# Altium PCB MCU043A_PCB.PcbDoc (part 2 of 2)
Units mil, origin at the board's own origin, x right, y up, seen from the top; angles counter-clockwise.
Board outline 3935 x 1020 mil, 2 copper layers (Top Layer, Bottom Layer), stack 62 mil thick; 69 components, 49 nets, 220 pads, 91 vias.
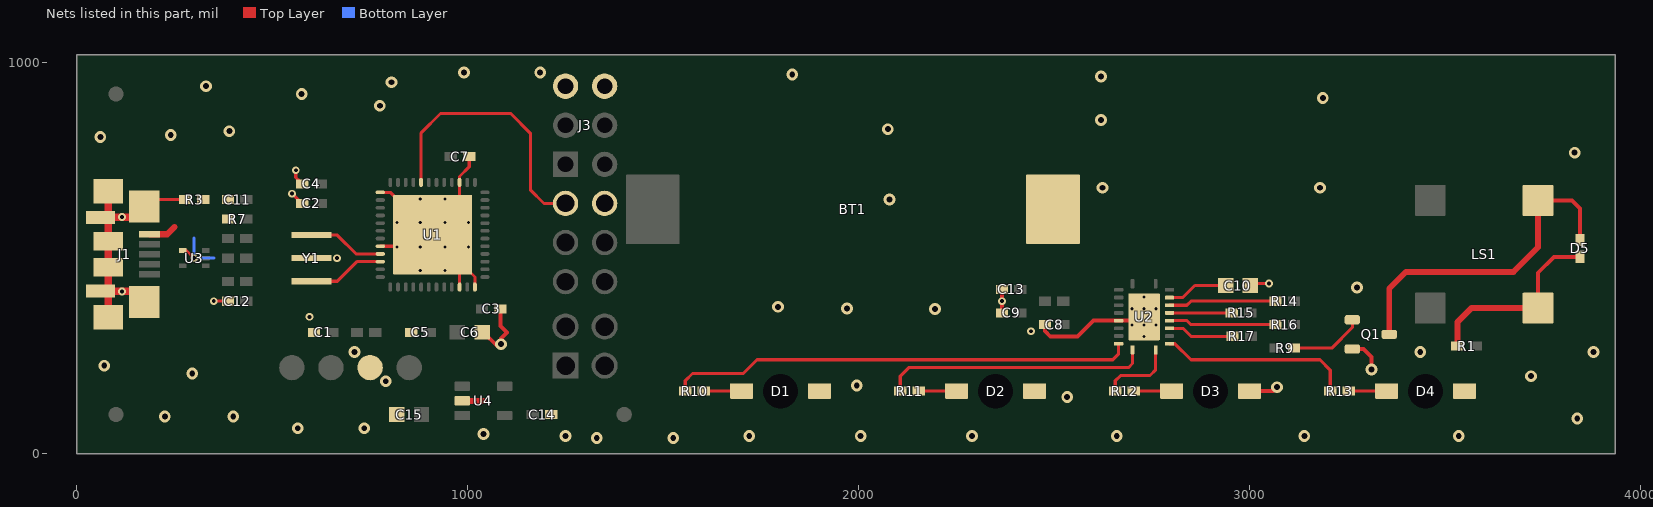
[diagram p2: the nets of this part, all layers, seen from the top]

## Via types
v1: diameter 30, hole 15, Top Layer to Bottom Layer, tented both sides, 51 vias
v2: diameter 19.68, hole 7.87, Top Layer to Bottom Layer, 20 vias
v3: diameter 20, hole 10, Top Layer to Bottom Layer, tented both sides, 20 vias

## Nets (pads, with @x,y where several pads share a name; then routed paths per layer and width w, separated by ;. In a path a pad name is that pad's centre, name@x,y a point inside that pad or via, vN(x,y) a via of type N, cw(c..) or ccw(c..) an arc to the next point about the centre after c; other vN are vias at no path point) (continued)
GND: C1.2 C2.2 C3.2 C4.2 C5.2 C6.2 C7.2 C11.2 C12.2 C14.2 C15.2 J1.5 J3.5 pad.1@750,220 R3.2 R7.1 U1.10 U1.12 U1.27 U1.37 U1.44 U1.49 U3.4 U4.2 Y1.2 | length 1260.8
  Top Layer w8: U3.4@270.47,519.68 280.32,519.68 v3(300,500) ; v3(350,390) C12.2@386.38,390 ; v3(550,665) 551.38,665 C2.2@576.38,640 ; v3(560,725) 560,706.38 570,696.38 C4.2@576.38,690 ; U1.44@776.14,530.47 880.47,530.47 U1.49@910,560 ; U1.37@776.14,668.27 801.73,668.27 v2(878.37,591.63) U1.49@910,560 ; U1.10@978.9,426.14 U1.49@978.9,489 ; U1.49@978.9,628.9 U1.27@978.9,693.86 978.9,708.9 1003.62,733.62 C7.2@1003.62,760 ; U1.12@1018.27,426.14 1018.27,451.73 v2(941.63,528.37) U1.49@910,560
  Top Layer w10: C1.2@600,303.62 C1.2@606.38,310 ; C6.2@1040.43,310 1075.43,275 1080.43,280 v1(1085,280) 1085,295 1100,310 1083.62,326.38 C3.2@1083.62,370
  Top Layer w15: U4.2@985.87,135 1040,135
  Top Layer w16: J1.5@185.51,561.18 231.18,561.18 250,580
  Bottom Layer w8: 300,551 v3(300,500) 350,500
  other v1: 1250,45 1040,50 565,65 735,65 225,95 400,95 790,185 295,205 70,225 710,260 60,810 240,815 390,825 775,890 575,920 330,940 805,950 990,975 1185,975
  other v2: 878.37,468.46 941.63,468.46 818.46,528.37 878.37,528.37 1001.54,528.37 818.46,591.63 941.63,591.63 1001.54,591.63 878.37,651.54 941.63,651.54
  other v3: 595,350 665,500
GND_Target: BT1.2 C8.2 C9.2 C10.2 C13.2 D1.2 D2.2 D3.2 D4.2 J3.6 pad.1@1350,640 Q1.2 U2.6 U2.21@2730,350 | length 571.6
  Top Layer w8: C10.2@3001.49,430 3006.49,435 v3(3050,435)
  Top Layer w10: v1(1995,174.09) v1@1995.32,174.09 ; C9.2@2366.37,360 C13.2@2366.37,420 ; C8.2@2476.37,330 2476.37,313.63 2490,300 2560,300 2600.15,340.16 U2.6@2665.04,340.16 2720.16,340.16 U2.21@2730,350 ; D3.2@2999.41,160 3060,160 v1(3070,170) ; Q1.2@3262.76,267.6 3291.31,267.6 3311.73,247.18 v1(3311.73,215)
  other v1: 1330,40 1525.43,40 1720,45 2005,45 2290,45 2660,45 3140,45 3535,45 3838.17,90 2533.2,145 3720,198.1 3436.44,260 3880,260 2195,370.16 1970,371.43 1793.59,375.5 3275,425 2078.86,650 2623.59,680 3180,680 3831.54,770 2074.48,830 2620,853.3 3187.39,910 2620,965 1830,970
  other v2: 2730,299.81 2699.48,329.33 2730,329.33 2760.51,329.33 2699.48,370.67 2730,370.67 2760.51,370.67 2730,400.2
  other v3: 2440.65,313 2366.37,390
LED1: D1.1 R10.1 | length 97
  Top Layer w8: R10.1@1607.24,160 D1.1@1704.21,160
LED2: D2.1 R11.1 | length 97
  Top Layer w8: R11.1@2153.62,160 D2.1@2250.59,160
LED3: D3.1 R12.1 | length 97
  Top Layer w8: R12.1@2703.62,160 D3.1@2800.59,160
LED4: D4.1 R13.1 | length 97
  Top Layer w8: R13.1@3253.62,160 D4.1@3350.59,160
MCU_IRQ: pad.1@1250,640 U1.32 | length 696.9
  Top Layer w8: U1.32@880.47,693.86 880.47,820.47 930,870 1110,870 1160,820 1160,675 1195,640 pad.1@1250,640
NetD5_1: D5.1 LS1.1 R1.1 | length 497.2
  Top Layer w10: LS1.1@3737.8,372.2 3737.8,462.8 3778.35,503.35 D5.1@3845,503.35
  Top Layer w15: R1.1@3531.38,275 3531.38,336.38 3567.2,372.2 LS1.1@3737.8,372.2
NetD5_2: D5.2 LS1.2 Q1.3 | length 858
  Top Layer w10: LS1.2@3737.8,647.8 3824.69,647.8 3845,627.49 D5.2@3845,546.65
  Top Layer w15: Q1.3@3357.24,305 3357.24,422.24 3400,465 3675,465 3737.8,527.8 LS1.2@3737.8,647.8
NetQ1_1: Q1.1 R9.2 | length 190.6
  Top Layer w8: R9.2@3113.62,270 3210,270 3262.76,322.76 Q1.1@3262.76,342.4
NetR10_2: R10.2 U2.9 | length 1189.5
  Top Layer w8: R10.2@1556.38,160 1556.38,186.38 1575,205 1705,205 1740,240 2210,240 2650,240 2665.04,255.04 U2.9@2665.04,281.1
NetR11_2: R11.2 U2.10 | length 680.6
  Top Layer w8: R11.2@2106.38,160 2106.38,198.32 2128.06,220 2690,220 2700.47,230.47 U2.10@2700.47,265.36
NetR12_2: R12.2 U2.11 | length 192
  Top Layer w8: R12.2@2656.38,160 2656.38,186.38 2670,200 2745,200 2759.53,214.53 U2.11@2759.53,265.36
NetR13_2: R13.2 U2.12 | length 493
  Top Layer w8: U2.12@2794.96,281.1 2808.9,281.1 2850,240 3180,240 3206.38,213.62 R13.2@3206.38,160
NetR14_2: R14.2 U2.17 | length 275.8
  Top Layer w8: U2.17@2794.96,379.53 2839.52,379.53 2850,390 R14.2@3066.37,390
NetR15_2: R15.2 U2.16 | length 159.4
  Top Layer w8: U2.16@2794.96,359.84 R15.2@2954.4,359.84
NetR16_2: R16.2 U2.15 | length 275.6
  Top Layer w8: U2.15@2794.96,340.16 2839.84,340.16 2850,330 R16.2@3066.37,330
NetR17_2: R17.2 U2.14 | length 169.9
  Top Layer w8: U2.14@2794.96,320.47 2829.53,320.47 2850,300 R17.2@2956.37,300
NetU1_45: U1.45 Y1.3 | length 196.1
  Top Layer w8: Y1.3@600,559.06 665.94,559.06 714.21,510.79 U1.45@776.14,510.79
NetU1_46: U1.46 Y1.1 | length 196.9
  Top Layer w8: Y1.1@600,440.94 665.94,440.94 716.1,491.1 U1.46@776.14,491.1
USB_SHIELD: J1.6 J1.7 J1.8 J1.9 J1.10 J1.11 J1.12 J1.13 R3.1 | length 681
  Top Layer w8: J1.6@172.52,632.05 190.47,650 R3.1@276.38,650
  Top Layer w20: J1.12@60.51,415.51 J1.12@80,415.51 ; J1.9@60.51,604.49 J1.9@80,604.49 ; J1.13@80,348.58 J1.12@80,415.51 ; J1.8@80,671.42 J1.9@80,604.49 ; J1.7@172.52,387.95 144.96,415.51 J1.12@80,415.51 ; J1.6@172.52,632.05 144.96,604.49 J1.9@80,604.49 ; J1.12@80,415.51 J1.11@80,476.54 J1.10@80,543.46 J1.9@80,604.49
  other v3: 115,415 115,605
VREG: C10.1 U2.18 | length 156.3
  Top Layer w8: U2.18@2794.96,399.21 2829.21,399.21 2860,430 C10.1@2938.5,430
pads on no net: D1. D2. D3. D4. FID1.1 FID2.1 FID3.1 H1.0 H2.0 H3.0 H4.0 J1.4 J2.3 LS1.3 LS1.4 SH-J1.0 SH-J2.0 SH-J3.0 SH-J4.0 U1.1 U1.2 U1.3 U1.4 U1.5 U1.6 U1.8 U1.9 U1.14 U1.15 U1.16 U1.17 U1.18 U1.19 U1.20 U1.21 U1.22 U1.23 U1.24 U1.25 U1.26 U1.29 U1.35 U1.36 U2.1 U2.2 U2.19 U2.20 U2.21@2707.95,308.66 U2.21@2707.95,350 U2.21@2707.95,391.34 U2.21@2752.04,308.66 U2.21@2752.04,350 U2.21@2752.04,391.34 U3.2 U4.4

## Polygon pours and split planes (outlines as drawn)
GND on Top Layer "Top Layer-No Net 1" (solid, remove dead copper, pour order 4): 0,1020 0,0 1280,0 1280,1020
GND_Target on Top Layer "Top Layer-No Net" (hatched 45Degree grid 40 track 8, remove dead copper, pour order 0): 1320,1020 1320,0 3935,0 3935,1020
GND on Bottom Layer "Bottom Layer-No Net 2" (solid, remove dead copper, pour order 8): 0,1020 1280,1020 1280,0 0,0
USB_SHIELD on Bottom Layer "Bottom Layer-No Net 1" (solid, remove dead copper, pour order 6): 0,711.19 250,711.19 250,310 0,310
GND_Target on Bottom Layer "Bottom Layer-No Net" (solid, remove dead copper, pour order 2): 1320,460 1320,0 3935,0 3935,460
GND_Target on Bottom Layer "Bottom Layer-No Net 3" (hatched 45Degree grid 40 track 8, remove dead copper, pour order 10): 1320,1020 3935,1020 3935,450 1320,450

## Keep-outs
Keep-Out Layer:
  text ".Layer_Name" at -213,-2348.49 h60

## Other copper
Top Layer:
  text ".Layer_Name" at -213,-2348.49 h60
Bottom Layer:
  rectangle net CAP4: 3250,510 3650,910
  rectangle net CAP1: 1600,510 2000,910
  rectangle net CAP2: 2150,510 2550,910
  rectangle net CAP3: 2700,510 3100,910
  text ".Layer_Name" at -213,-2348.49 h60

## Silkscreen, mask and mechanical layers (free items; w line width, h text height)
Top Overlay:
  lines w10: 1300,10 1300,28.19 ; 1300,87.16 1300,137.16 ; 1300,197.16 1300,246.14 ; 1300,305.12 1300,355.12 ; 1300,414.09 1300,464.09 ; 1300,523.07 1300,573.07 ; 1300,632.05 1300,682.05 ; 1300,742.05 1300,791.02 ; 1300,850 1300,900 ; 1300,960 1300,1008.98 ; 3795,370 3845,370 ; 3820,345 3820,395
  text "'.PRJ_Number'.PCB_Rev" at 2880,885.45 h80
  text "CAPTIVATE - HID BRIDGE" at 510,850 h60
  text "BAT" at 1945,625 h30
  text "T" at 540,145 h30
  text "R" at 640,145 h30
  text "G" at 740,145 h30
  text "V" at 840,145 h30
  text ".Layer_Name" at -213,-2348.49 h60
Bottom Overlay:
  rectangle: 1450,185 1510,195
  region: 1510,305 1510,365 1500,365 1500,305
  lines w10: 1300,10 1300,28.19 ; 1300,88.19 1300,137.16 ; 1300,196.14 1300,246.14 ; 1300,306.14 1300,355.12 ; 1300,415.12 1300,464.09 ; 1300,524.09 1300,573.07 ; 1300,633.07 1300,682.05 ; 1300,741.02 1300,791.02 ; 1300,851.02 1300,900 ; 1300,960 1300,1008.98 ; 1430,215 1530,215 ; 1480,285 1480,385 ; 1875,480 1875,310 1945,310 ; 2215,310 2285,310 2285,480 ; 2425,480 2425,310 2495,310 ; 2765,310 2835,310 2835,480 ; 2975,480 2975,310 3045,310 ; 3315,310 3385,310 3385,480 ; 1430,165 1430,265 1530,265 1530,165 1430,165 ; 1430,285 1530,285 1530,385 1430,385 1430,285 ; 1605,510 2005,510 2005,910 1605,910 1605,510 ; 2155,510 2555,510 2555,910 2155,910 2155,510 ; 2705,510 3105,510 3105,910 2705,910 2705,510 ; 3255,510 3655,510 3655,910 3255,910 3255,510
  text "GND" at 1070,960 h40 r180
  text "1" at 1626.64,890 h150 r180
  text "2" at 2175,890 h150 r180
  text "3" at 2722.98,890 h150 r180
  text "4" at 3275,890 h150 r180
  text "TXD" at 1070,860 h40 r180
  text "RXD" at 1070,760 h40 r180
  text "C" at 1732.25,730 h300 r180
  text "E" at 2292.25,730 h300 r180
  text "G" at 2835,730 h300 r180
  text "B" at 3400,730 h300 r180
  text "GND" at 1420,660 h40 r180
  text "IRQ" at 1069.74,658.7 h40 r180
  text "SCL" at 1070,560 h40 r180
  text "TEST" at 1420,560 h40 r180
  text "SDA" at 1070,460 h40 r180
  text "RST" at 1420,460 h40 r180
  text "D" at 2015.85,400.47 h300 r180
  text "F" at 2575,400 h300 r180
  text "A" at 3105,400 h300 r180
  text "www.ti.com/captivate" at 210,390 h80 r180
  text "BAT" at 1565,365 h80 r180
  text "EVM430-CAPMINI" at 180,290 h100 r180
  text "USB" at 1565,245 h80 r180
  text ".Layer_Name" at -213,-2348.49 h60
Top Paste:
  text ".Layer_Name" at -213,-2348.49 h60
Bottom Paste:
  text ".Layer_Name" at -213,-2348.49 h60
Top Solder:
  text ".Layer_Name" at -213,-2348.49 h60
  text ".Layer_Name" at -213,-2348.49 h60
Bottom Solder:
  text ".Layer_Name" at -213,-2348.49 h60
Drill Guide:
  text ".Layer_Name" at -213,-2348.49 h60
M1 Board Outline:
  lines w10: 0,0 0,1020 3910,1020 3935,1020 3935,0 750,0 530,0 0,0
  text ".Layer_Name" at -213,-2348.49 h60
M2 Board Dimensions:
  rectangle: -790,-1765 -665,-1640
  rectangle: -665,-1890 -290,-1765
  lines w7: -790,-1765 210,-1765 ; -665,-1890 -665,-1640 ; -540,-1890 -540,-1640 ; -290,-1890 -290,-1640 ; -40,-1890 -40,-1640 ; -790,-1890 210,-1890 210,-1640 -790,-1640 -790,-1890
  text ".Layer_Name" at -213,-2348.49 h60
M3 3D STEP Top:
  text ".Layer_Name" at -213,-2348.49 h60
M4 3D STEP Bottom:
  text ".Layer_Name" at -213,-2348.49 h60
M5 Assembly Top:
  lines w10: -1082,-2420.17 5518,-2420.17 ; -1082,-2216.83 5520,-2216.83 ; -1082,-2013.5 -1082,-2623.5 2923,-2623.5 5520,-2623.5 5520,-2013.5 -1081.5,-2013.5 -1081.5,-2623.5 494,-2623.5 ; 1383,-2623.5 1383,-2013.5 ; 2650,-2216.83 2650,-2013.5 ; 3490,-2216.83 3490,-2013.5 ; 4112,-2630 4112,-2427.17
  text "COMPONENTS MARKED 'DNP' SHOULD NOT BE POPULATED." at 363.5,-1808.5 h60
  text "ASSEMBLY VARIANT:" at 363,-1924 h60
  text ".VariantName" at 1399,-1924 h60
  text "PCB VIEWED FROM TOP SIDE" at -1018.5,-2145.67 h60
  text "BOARD #:" at 1458,-2145.67 h60
  text ".PRJ_Number" at 2003.5,-2145.67 h60
  text "REV:" at 2848,-2145.67 h60
  text ".PCB_Rev" at 3139.5,-2145.67 h60
  text "SVN REV:" at 3686,-2145.67 h60
  text ".VersionControl_RevNumber" at 4192,-2145.67 h60
  text "TID #:" at 1458,-2349 h60
  text ".TID" at 2003.5,-2349 h60
  text "PLOT NAME =" at -1018.5,-2554.34 h60
  text ".plot_File_Name" at -213,-2554.34 h60
  text "GENERATED    :" at 1460,-2554.34 h60
  text ".Print_Date" at 2329.5,-2554.34 h60
  text ".Print_Time" at 3058.5,-2554.34 h60
  text "TEXAS INSTRUMENTS" at 4323,-2554.34 h60
M6 Assembly Bottom:
  lines w10: -1082.5,-2217.33 5519.5,-2217.33 ; -1080.5,-2420.67 5519.5,-2420.67 ; 325.5,-2630.5 325.5,-2427.67 ; 947.5,-2217.33 947.5,-2014 ; 1787.5,-2217.33 1787.5,-2014 ; 3054.5,-2624 3054.5,-2014 ; 3943.5,-2624 5519,-2624 5519,-2014 -1082.5,-2014 -1082.5,-2624 1514.5,-2624 5519.5,-2624 5519.5,-2014
  text "COMPONENTS MARKED 'DNP' SHOULD NOT BE POPULATED." at 5312,-1808 h60
  text ".VariantName" at 4268,-1924 h60
  text "ASSEMBLY VARIANT:" at 5307,-1924 h60
  text ".VersionControl_RevNumber" at 245.5,-2146.17 h60
  text "SVN REV:" at 751.5,-2146.17 h60
  text ".PCB_Rev" at 1298,-2146.17 h60
  text "REV:" at 1589.5,-2146.17 h60
  text ".PRJ_Number" at 2434,-2146.17 h60
  text "BOARD #:" at 2979.5,-2146.17 h60
  text "PCB VIEWED FROM BOTTOM SIDE" at 5456,-2146.17 h60
  text ".TID" at 2434,-2349.5 h60
  text "TID #:" at 2979.5,-2349.5 h60
  text "TEXAS INSTRUMENTS" at 114.5,-2554.84 h60
  text ".Print_Time" at 1379,-2554.84 h60
  text ".Print_Date" at 2108,-2554.84 h60
  text "GENERATED    :" at 2977.5,-2554.84 h60
  text ".plot_File_Name" at 4650.5,-2554.84 h60
  text "PLOT NAME =" at 5456,-2554.84 h60
M9 Title Sheet:
  drawing of 57 lines, arcs and shapes, not listed
  text "1" at -50.16,6546.5 h70
  text "2" at 2445.5,6546.5 h70
  text "3" at 4934.84,6546.5 h70
  text "4" at 7441.51,6546.5 h70
  text "5" at 9940.5,6546.5 h70
  text "6" at 12445.5,6546.5 h70
  text "A" at -1206.5,5403.5 h70
  text "A" at 13593.5,5403.5 h70
  text "B" at -1206.5,3023.5 h70
  text "B" at 13593.5,3023.5 h70
  text "C" at -1206.5,648.5 h70
  text "C" at 13593.5,648.5 h70
  text "PROJECT TITLE:" at 10553.5,-1212.5 h45
  text ".PRJ_Title" at 10603.5,-1345.83 h70
  text "DESIGNED FOR:" at 10553.5,-1513.5 h45
  text ".PRJ_Customer" at 10603.5,-1653.5 h70
  text "D" at -1206.5,-1721.5 h70
  text "D" at 13593.5,-1721.5 h70
  text "FILE NAME:" at 10553.5,-1813.5 h45
  text ".PCB_File_Name_No_Path" at 10603.5,-1933.5 h70
  text "Texas Instruments (TI) and/or its licensors do not warrant the accuracy or completeness of this specification" at 5584,-2095.34 h45
  text "ENGINEER:" at 10553.5,-2103.5 h45
  text "LAYOUT BY:" at 12058.5,-2103.5 h45
  text "or any information contained therein. TI and/or its licensors do not warrant that this design will meet" at 5539.01,-2208 h45
  text ".PRJ_Engineer" at 10603.5,-2258.49 h70
  text ".PCB_Layout" at 12109,-2258.49 h70
  text "the specifications, will be suitable for your application or fit for any particular purpose, or will operate in" at 5539.01,-2320.67 h45
  text ".Layer_Name" at -213,-2348.49 h60
  text "ALTIUM DESIGNER VERSION:" at 12058.5,-2413.5 h45
  text "an implementation. TI and/or its licensors do not warrant that the design is production worthy. You should" at 5539.01,-2433.33 h45
  text "completely validate and test your design implementation to confirm the system functionality for your application." at 5584,-2546 h45
  text ".print_Scale" at 10603.5,-2546.83 h70
  text ".Application_BuildNumber" at 12109,-2546.83 h70
  text "1" at -50.16,-2753.5 h70
  text "2" at 2445.5,-2753.5 h70
  text "3" at 4934.84,-2753.5 h70
  text "4" at 7441.51,-2753.5 h70
  text "5" at 9940.5,-2753.5 h70
  text "6" at 12445.5,-2753.5 h70
M10 Fab Notes:
  drawing of 173 lines, arcs and shapes, not listed
  text "DESIGN INFORMATION" at 11588.02,4711 h60
  text "MIN. TRACK WIDTH:" at 10943.46,4531 h60
  text "8" at 12039.7,4531 h60
  text "MIL" at 12194.46,4531 h60
  text "MIN. CLEARANCE:" at 10943.46,4399 h60
  text "0.2" at 11979.7,4399 h60
  text "mm" at 12194.46,4399 h60
  text "MIN. VIA PAD SIZE:" at 10943.46,4267 h60
  text "20" at 12009.71,4267 h60
  text "MIL" at 12194.46,4267 h60
  text "0.05mm (2MIL)" at 11638.46,4125.29 h60
  text "MINIMUM ANNULAR RING" at 10614.23,4121 h60
  text "EXTERNAL" at 12346.46,4121 h60
  text "PER" at 10814.23,4003 h60
  text "IPC-D-275 CLASS 2 LEVEL C" at 11034.23,4003 h60
  text "MIL, HOLES" at 12522.46,3890.71 h60
  text "+/-" at 12130,3890 h60
  text "+/-" at 12984,3890 h60
  text "REGISTRATION TOLERANCES:" at 10614.23,3885 h60
  text "METAL" at 11814,3885 h60
  text "5" at 12390.2,3885 h60
  text "3" at 13223.2,3885 h60
  text "MIL" at 13339.46,3885 h60
  text "+/-" at 12984,3772 h60
  text "HOLE SIZE TOLERANCE (UNLESS OTHERWISE SPECIFIED):" at 10614.23,3767 h60
  text "3" at 13223.2,3767 h60
  text "MIL" at 13339.46,3767 h60
  text "MATERIAL:" at 10539.46,3557.54 h60
  text "FR-4 High Tg" at 11525.9,3417.21 h60
  text "FR-408" at 10960.46,3408.64 h60
  text "OTHER" at 12448.46,3408.64 h60
  text "X" at 11371,3405 h60
  text "62 MIL (1.6mm) +/-10%" at 11280.56,3245.92 h60
  text "THICKNESS:" at 10614.23,3241.64 h60
  text "X" at 11152.4,3241.64 h60
  text "OTHER" at 12565.46,3241.64 h60
  text "TOLERANCE:" at 10614.23,3083.64 h60
  text "X" at 11453.53,3083.64 h60
  text "ANSI IPC-6012 TYPE 3 CLASS 2" at 11640.48,3083.64 h60
  text "OTHER +/-" at 11640.46,2927.64 h60
  text "BOW & TWIST:" at 10614.23,2770.64 h60
  text "X" at 11453.53,2770.64 h60
  text "ANSI IPC-6012 TYPE 3 CLASS 2" at 11640.48,2770.64 h60
  text "OTHER +/-" at 11640.46,2612.13 h60
  text "DRILLING:" at 10539.46,2473.64 h60
  text "REFERENCE:" at 10614.23,2356.64 h60
  text "X" at 11262.46,2356.64 h60
  text "AS SHOWN" at 11449.46,2356.64 h60
  text "X" at 12163.46,2356.64 h60
  text "NC_DRILL FILES" at 12300.46,2356.64 h60
  text "PTH COPPER THICKNESS:" at 10614.23,2198.64 h60
  text "X" at 11744.46,2198.64 h60
  text "20-30 um" at 11881.46,2198.64 h60
  text "OTHER" at 12598.46,2198.64 h60
  text "BOARD FINISH:" at 10539.46,2039.64 h60
  text "SILKSCREEN:" at 10694.68,1921.64 h60
  text "X" at 11643.46,1921.64 h60
  text "TOP" at 11769.46,1921.64 h60
  text "X" at 12153.46,1921.64 h60
  text "BOTTOM" at 12280.46,1921.64 h60
  text "SILKSCREEN COLOR:" at 10694.68,1754.64 h60
  text "X" at 11642.42,1754.64 h60
  text "WHITE" at 11769.46,1754.64 h60
  text "OTHER" at 12280.46,1754.64 h60
  text "X" at 12365,1605 h60
  text "BLACK" at 12933.46,1600.44 h60
  text "GREEN" at 11900.46,1595.44 h60
  text "OTHER" at 12518.46,1595.44 h60
  text "SOLDER RESIST COLOR:" at 10694.68,1584.64 h60
  text "MATTE" at 11900.46,1425.44 h60
  text "SEMI-GLOSS" at 12518,1424.8 h60
  text "X" at 12368.42,1420.44 h60
  text "IMMERSION GOLD (ENIG)" at 11600.46,1236.92 h60
  text "ENEPIG" at 12938,1233.64 h60
  text "SURFACE FINISH:" at 10539.46,1232.64 h60
  text "IMM. TIN/SILVER OR EQUIV" at 10869,1075.64 h60
  text "OTHER" at 12300.46,1075.64 h60
  text "X" at 10707,1075 h60
  text "ARRAY/PANEL:" at 10539.46,896.64 h60
  text "X" at 11413.51,892.64 h60
  text "CUT AND TRIM PER M1 BOARD OUTLINE" at 11600.46,892.35 h60
  text "N.C. ROUTE" at 11600.46,740.64 h60
  text "X" at 12279.46,740.64 h60
  text "V. SCORE" at 12466.46,740.64 h60
  text "CERTIFICATION:" at 10539.46,603.64 h60
  text "MATERIALS AND WORKMANSHIP FOR ALL PCBS" at 11264.46,603.64 h60
  text "TO MEET OR EXCEED THE REQUIREMENTS OF:" at 11264.46,505.64 h60
  text "X" at 10890.96,369.13 h60
  text "ANSI IPC-A-600F CLASS ->" at 11029.96,369.13 h60
  text "X" at 12669.02,369.13 h60
  text "2" at 12787.96,369.14 h60
  text "1" at 12472.96,367.64 h60
  text "3" at 13141.96,367.64 h60
  text "X" at 11705.02,209.64 h60
  text "RoHS" at 11841.96,209.64 h60
  text "OTHER" at 12486.36,209.64 h60
  text "PER ORDER" at 12883.42,209.64 h60
  text "ALL BOARDS MUST MEET OR EXCEED UL94-V0 REQUIREMENTS." at 10567,44 h60
  text "PCB MUST BEAR THE UL94V-0 UL REGISTERED MATERIAL ID NUMBER" at 10567,-76 h60
  text "ADDITIONAL REQUIREMENTS:" at 10539.46,-249.36 h60
  text "MICROSECTION:" at 10614.23,-364.36 h60
  text "YES" at 11519.96,-364.36 h60
  text "REQUIRED" at 12381.46,-520.51 h60
  text "BARE BOARD ELEC. TEST:" at 10614.23,-523.36 h60
  text "NONE" at 11919.96,-523.36 h60
  text "X" at 12846.46,-523.36 h60
  text "PER ORDER" at 12973.46,-523.36 h60
  text ".Layer_Name" at -213,-2348.49 h60
M11 Gerber Information:
  lines w10: -1082,-2420.17 5518,-2420.17 ; -1082,-2216.83 5520,-2216.83 ; -1082,-2013.5 -1082,-2623.5 2923,-2623.5 5520,-2623.5 5520,-2013.5 -1081.5,-2013.5 -1081.5,-2623.5 494,-2623.5 ; 1383,-2623.5 1383,-2013.5 ; 2650,-2216.83 2650,-2013.5 ; 3490,-2216.83 3490,-2013.5 ; 4112,-2630 4112,-2427.17
  text "ALL ARTWORK VIEWED FROM TOP SIDE" at -1018.5,-2145.67 h60
  text "BOARD #:" at 1458,-2145.67 h60
  text ".PRJ_Number" at 2003.5,-2145.67 h60
  text "REV:" at 2848,-2145.67 h60
  text ".PCB_Rev" at 3139.5,-2145.67 h60
  text "SVN REV:" at 3686,-2145.67 h60
  text ".VersionControl_RevNumber" at 4192,-2145.67 h60
  text "LAYER NAME =" at -1018.5,-2348.49 h60
  text "TID #:" at 1458,-2349 h60
  text ".TID" at 2003.5,-2349 h60
  text "PLOT NAME =" at -1018.5,-2554.34 h60
  text ".plot_File_Name" at -213,-2554.34 h60
  text "GENERATED    :" at 1460,-2554.34 h60
  text ".Print_Date" at 2329.5,-2554.34 h60
  text ".Print_Time" at 3058.5,-2554.34 h60
  text "TEXAS INSTRUMENTS" at 4323,-2554.34 h60
M12 Stackup:
  drawing of 191 lines, arcs and shapes, not listed
  text "Layer" at 9007.84,6340 h60
  text "Name" at 9417.76,6340 h60
  text "Material" at 10347.5,6340 h60
  text "Thickness" at 11207.27,6340 h60
  text "Constant" at 11857.1,6340 h60
  text "Board Layer Stack" at 12426.96,6340 h60
  text "1" at 9007.84,6220 h60
  text "Top Overlay" at 9417.76,6220 h60
  text "2" at 9007.84,6100 h60
  text "Top Solder" at 9417.76,6100 h60
  text "Solder Resist" at 10347.5,6100 h60
  text "0.40mil" at 11207.27,6100 h60
  text "3.5" at 11857.1,6100 h60
  text "3" at 9007.84,5980 h60
  text "Top Layer" at 9417.76,5980 h60
  text "Copper" at 10347.5,5980 h60
  text "1.40mil" at 11207.27,5980 h60
  text "4" at 9007.84,5860 h60
  text "Dielectric1" at 9417.76,5860 h60
  text "FR-4" at 10347.5,5860 h60
  text "59.20mil" at 11207.27,5860 h60
  text "4.8" at 11857.1,5860 h60
  text "5" at 9007.84,5740 h60
  text "Bottom Layer" at 9417.76,5740 h60
  text "Copper" at 10347.5,5740 h60
  text "1.40mil" at 11207.27,5740 h60
  text "6" at 9007.84,5620 h60
  text "Bottom Solder" at 9417.76,5620 h60
  text "Solder Resist" at 10347.5,5620 h60
  text "0.40mil" at 11207.27,5620 h60
  text "3.5" at 11857.1,5620 h60
  text "7" at 9007.84,5500 h60
  text "Bottom Overlay" at 9417.76,5500 h60
  text ".Layer_Name" at -213,-2348.49 h60
M13 Component Bodies Top:
  text ".Layer_Name" at -213,-2348.49 h60
M14 Component Bodies Bottom:
  text ".Layer_Name" at -213,-2348.49 h60
M15 Courtyards Top:
  text ".Layer_Name" at -213,-2348.49 h60
M16 Courtyards Bottom:
  text ".Layer_Name" at -213,-2348.49 h60
Drill Drawing:
  circle w10: c4573.54,1156.58 r27.56
  lines w10: 4545.98,1018.78 4559.76,1018.78 4559.76,1004.99 4587.32,1004.99 4587.32,1018.78 4601.1,1018.78 4601.1,1046.34 4587.32,1046.34 4587.32,1060.12 4559.76,1060.12 4559.76,1046.34 4545.98,1046.34 4545.98,1018.78 ; 4545.98,1253.05 4601.1,1253.05 4601.1,1308.17 4545.98,1308.17 4545.98,1253.05 ; 4545.98,1377.07 4545.98,1390.86 4559.76,1404.64 4545.98,1418.42 4545.98,1432.2 4559.76,1432.2 4573.54,1418.42 4587.32,1432.2 4601.1,1432.2 4601.1,1418.42 4587.32,1404.64 4601.1,1390.86 4601.1,1377.07 4587.32,1377.07 4573.54,1390.86 4559.76,1377.07 4545.98,1377.07 ; 4545.98,1501.1 4573.54,1514.88 4601.1,1501.1 4587.32,1528.66 4601.1,1556.22 4573.54,1542.44 4545.98,1556.22 4559.76,1528.66 4545.98,1501.1 ; 4545.98,1638.91 4559.76,1638.91 4573.54,1625.13 4587.32,1638.91 4601.1,1638.91 4587.32,1652.69 4601.1,1666.47 4587.32,1666.47 4573.54,1680.25 4559.76,1666.47 4545.98,1666.47 4559.76,1652.69 4545.98,1638.91 ; 4545.98,1749.15 4601.1,1749.15 4601.1,1804.28 4545.98,1804.28 4545.98,1749.15 ; 4557,1760.18 4590.08,1760.18 4590.08,1793.25 4557,1793.25 4557,1760.18
  lines w12: 4496,967.79 7722.8,967.79 ; 4496,1835.97 7722.8,1835.97 ; 4833.36,843.76 4833.36,1960 ; 5165.06,843.76 5165.06,1960 ; 5800.91,843.76 5800.91,1960 ; 6059.71,843.76 6059.71,1960 ; 6434.46,843.76 6434.46,1960 ; 7157,843.76 7157,1960 ; 4496,843.76 7722.8,843.76 7722.8,1960 4496,1960 4496,843.76
  text "Symbol" at 4570.42,1873.18 h72
  text "Quantity" at 4870.57,1873.18 h72
  text "Finished Hole Size" at 5202.26,1873.18 h72
  text "Plated" at 5838.12,1873.18 h72
  text "Hole Type" at 6096.92,1873.18 h72
  text "Drill Layer Pair" at 6471.67,1873.18 h72
  text "Hole Tolerance" at 7194.21,1873.18 h72
  text "4" at 4870.57,1749.15 h60
  text "88.58mil (2.250mm)" at 5202.26,1749.15 h60
  text "NPTH" at 5838.12,1749.15 h60
  text "Round" at 6096.92,1749.15 h60
  text "Top Layer - Bottom Layer" at 6471.67,1749.15 h60
  text "20" at 4870.57,1625.13 h60
  text "7.87mil (0.200mm)" at 5202.26,1625.13 h60
  text "PTH" at 5838.12,1625.13 h60
  text "Round" at 6096.92,1625.13 h60
  text "Top Layer - Bottom Layer" at 6471.67,1625.13 h60
  text "20" at 4870.57,1501.1 h60
  text "10.00mil (0.254mm)" at 5202.26,1501.1 h60
  text "PTH" at 5838.12,1501.1 h60
  text "Round" at 6096.92,1501.1 h60
  text "Top Layer - Bottom Layer" at 6471.67,1501.1 h60
  text "51" at 4870.57,1377.07 h60
  text "15.00mil (0.381mm)" at 5202.26,1377.07 h60
  text "PTH" at 5838.12,1377.07 h60
  text "Round" at 6096.92,1377.07 h60
  text "Top Layer - Bottom Layer" at 6471.67,1377.07 h60
  text "6" at 4870.57,1253.05 h60
  text "40.00mil (1.016mm)" at 5202.26,1253.05 h60
  text "PTH" at 5838.12,1253.05 h60
  text "Round" at 6096.92,1253.05 h60
  text "Top Layer - Bottom Layer" at 6471.67,1253.05 h60
  text "6" at 4870.57,1129.02 h60
  text "45.00mil (1.143mm)" at 5202.26,1129.02 h60
  text "PTH" at 5838.12,1129.02 h60
  text "Round" at 6096.92,1129.02 h60
  text "Top Layer - Bottom Layer" at 6471.67,1129.02 h60
  text "4" at 4870.57,1004.99 h60
  text "47.24mil (1.200mm)" at 5202.26,1004.99 h60
  text "PTH" at 5838.12,1004.99 h60
  text "Round" at 6096.92,1004.99 h60
  text "Top Layer - Bottom Layer" at 6471.67,1004.99 h60
  text "111 Total" at 4870.57,880.97 h60
  text ".Layer_Name" at -213,-2348.49 h60
M17 Embedded Cavity:
  text ".Layer_Name" at -213,-2348.49 h60
M18 Embedded Assembly:
  text ".Layer_Name" at -213,-2348.49 h60
M19 Embedded Keepout:
  text ".Layer_Name" at -213,-2348.49 h60

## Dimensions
-790,-1890 to 210,-1890 on M2 Board Dimensions
0,1020 to 3935,1020 on M2 Board Dimensions
3935,1020 to 3935,0 on M2 Board Dimensions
